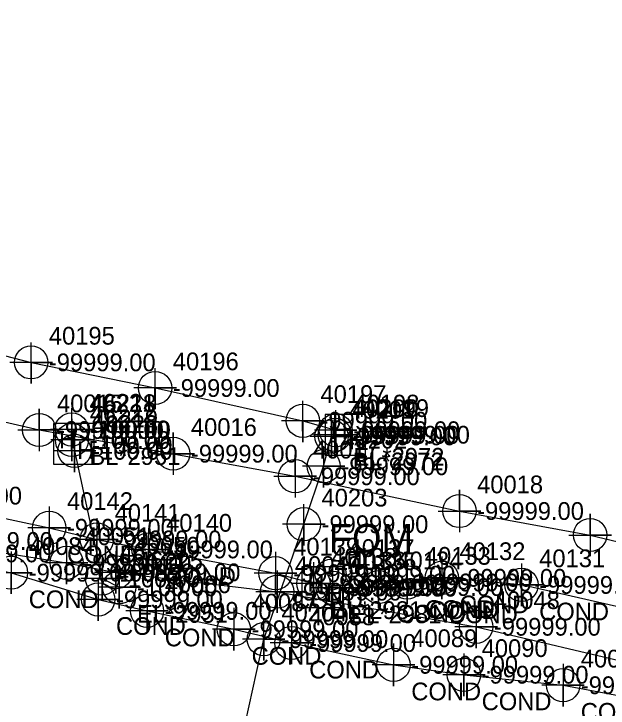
# Model space of a CAD drawing. Extents: x 2083698 to 2094313, y 743246 to 752873.
# Drawn here: x 2090821 to 2090904.8, y 744569.6 to 744667.4 of the extents above; entities that cross this region are included whole.
import ezdxf

# ---------------------------------------------------------------- set-up
doc = ezdxf.new("R2010")
doc.units = 0
for name, color, linetype in [('COGO Default Chain', 7, 'Continuous'), ('COGO Default Curve', 7, 'Continuous'), ('COGO Default Parcel', 7, 'Continuous'), ('COGO Default Point Number', 7, 'Continuous'), ('COGO Default Spiral', 7, 'Continuous'), ('Default Symbol CELL', 7, 'Continuous'), ('Default Symbol Cogo Number', 7, 'Continuous'), ('Exist Other Culture Fence Line', 7, 'Continuous'), ('Exist Property Corner CELL', 7, 'Continuous'), ('Exist Property Corner Cogo Comment', 7, 'Continuous'), ('Exist Property Deed Book Text', 7, 'Continuous'), ('Exist Property Iron Pin CELL', 7, 'Continuous'), ('Exist Property Iron Pin Cogo Elevation', 7, 'Continuous'), ('Exist Property Iron Pin Cogo Number', 7, 'Continuous'), ('Exist Property Iron Pin Leader', 7, 'Continuous'), ('Exist Property Iron Pin Text', 7, 'Continuous'), ('Exist Property Line', 7, 'Continuous'), ('Exist Property Line Leader', 7, 'Continuous'), ('Exist Property Monument Leader', 7, 'Continuous'), ('Exist Property Monument Text', 7, 'Continuous'), ('Exist Property Owner Text', 7, 'Continuous'), ('Exist Right of Way Line', 7, 'Continuous'), ('Exist Right of Way Line Leader', 7, 'Continuous'), ('Exist Right of Way Line Text', 7, 'Continuous'), ('Exist Utilities Gas UG Line SUE LOS B', 7, 'Continuous'), ('Exist Utilities Other Located Object CELL', 7, 'Continuous'), ('Exist Utilities Other Located Object Text', 7, 'Continuous'), ('Exist Utilities Power Joint Use Telephone Cogo Elevation', 7, 'Continuous'), ('Exist Utilities Power Joint Use Telephone Cogo Number', 7, 'Continuous'), ('Exist Utilities Power UG Cable SUE LOS B', 7, 'Continuous'), ('Exist Utilities Telephone UG Conduit SUE LOS B', 7, 'Continuous'), ('Exist Utilities TV UG Cable SUE LOS B', 7, 'Continuous'), ('Exist Utilities Water UG Line SUE LOS B', 7, 'Continuous'), ('Old_Level_20', 7, 'Continuous'), ('Scratch_Level_0', 7, 'Continuous'), ('Scratch_Level_2', 7, 'Continuous'), ('Scratch_Level_3', 7, 'Continuous'), ('Scratch_Level_5', 7, 'Continuous')]:
    doc.layers.add(name, color=color, linetype=linetype)

msp = doc.modelspace()

# ---------------------------------------------------------------- linework, layer by layer
at = {"layer": 'COGO Default Curve'}
for points in [[(2090821.585, 744608.753), (2090827.585, 744608.753), (2090824.585, 744608.753), (2090824.585, 744611.753), (2090824.585, 744605.753)], [(2090840.465, 744605.417), (2090846.465, 744605.417), (2090843.465, 744605.417), (2090843.465, 744608.417), (2090843.465, 744602.417)], [(2090857.667, 744602.233), (2090863.667, 744602.233), (2090860.667, 744602.233), (2090860.667, 744605.233), (2090860.667, 744599.233)], [(2090880.812, 744597.333), (2090886.812, 744597.333), (2090883.812, 744597.333), (2090883.812, 744600.333), (2090883.812, 744594.333)], [(2090899.238, 744593.955), (2090905.238, 744593.955), (2090902.238, 744593.955), (2090902.238, 744596.955), (2090902.238, 744590.955)]]:
    msp.add_lwpolyline(points, dxfattribs=at)
for centre in [(2090824.585, 744608.753), (2090843.465, 744605.417), (2090860.667, 744602.233), (2090883.812, 744597.333), (2090902.238, 744593.955)]:
    msp.add_circle(centre, 2.344, dxfattribs=at)
at = {"layer": 'COGO Default Point Number'}
for points in [[(2090828.444, 744593.031), (2090828.444, 744587.031), (2090828.444, 744590.031), (2090831.444, 744590.031), (2090825.444, 744590.031)], [(2090835.382, 744591.689), (2090835.382, 744585.689), (2090835.382, 744588.689), (2090838.382, 744588.689), (2090832.382, 744588.689)], [(2090858.125, 744588.967), (2090858.125, 744582.967), (2090858.125, 744585.967), (2090861.125, 744585.967), (2090855.125, 744585.967)], [(2090886.18, 744584.02), (2090886.18, 744578.02), (2090886.18, 744581.02), (2090889.18, 744581.02), (2090883.18, 744581.02)]]:
    msp.add_lwpolyline(points, dxfattribs=at)
for centre in [(2090828.444, 744590.031), (2090835.382, 744588.689), (2090858.125, 744585.967), (2090886.18, 744581.02)]:
    msp.add_circle(centre, 2.344, dxfattribs=at)
at = {"layer": 'COGO Default Spiral'}
msp.add_line((2090829.526, 744606.646), (2090829.526, 744606.646), dxfattribs=at)
msp.add_lwpolyline([(2090826.576, 744603.921), (2090832.326, 744603.921), (2090832.326, 744609.671), (2090826.576, 744609.671), (2090826.576, 744603.921)], dxfattribs=at)
at = {"layer": 'Exist Property Deed Book Text'}
msp.add_line((2090864.484, 744586.601), (2090864.484, 744586.601), dxfattribs=at)
msp.add_lwpolyline([(2090861.609, 744583.726), (2090867.359, 744583.726), (2090867.359, 744589.476), (2090861.609, 744589.476), (2090861.609, 744583.726)], dxfattribs=at)
at = {"layer": 'Exist Property Iron Pin CELL'}
for p, q in [((2090864.87, 744610.948), (2090864.87, 744605.223)), ((2090870.595, 744610.948), (2090864.87, 744610.948)), ((2090870.595, 744605.223), (2090870.595, 744610.948)), ((2090867.732, 744608.085), (2090867.732, 744608.085)), ((2090864.87, 744605.223), (2090870.595, 744605.223))]:
    msp.add_line(p, q, dxfattribs=at)
at = {"layer": 'Exist Property Iron Pin Text'}
for points in [[(2090829.15, 744611.832), (2090829.15, 744605.832), (2090829.15, 744608.832), (2090832.15, 744608.832), (2090826.15, 744608.832)], [(2090829.196, 744610.348), (2090829.196, 744604.348), (2090829.196, 744607.348), (2090832.196, 744607.348), (2090826.196, 744607.348)], [(2090829.547, 744608.818), (2090829.547, 744602.818), (2090829.547, 744605.818), (2090832.547, 744605.818), (2090826.547, 744605.818)], [(2090833.438, 744590.822), (2090833.438, 744584.822), (2090833.438, 744587.822), (2090836.438, 744587.822), (2090830.438, 744587.822)], [(2090835.861, 744589.588), (2090835.861, 744583.588), (2090835.861, 744586.588), (2090838.861, 744586.588), (2090832.861, 744586.588)]]:
    msp.add_lwpolyline(points, dxfattribs=at)
for centre in [(2090829.15, 744608.832), (2090829.196, 744607.348), (2090829.547, 744605.818), (2090833.438, 744587.822), (2090835.861, 744586.588)]:
    msp.add_circle(centre, 2.344, dxfattribs=at)
at = {"layer": 'Exist Property Line Leader'}
for points in [[(2090825.995, 744597.974), (2090825.995, 744591.974), (2090825.995, 744594.974), (2090828.995, 744594.974), (2090822.995, 744594.974)], [(2090832.713, 744596.332), (2090832.713, 744590.332), (2090832.713, 744593.332), (2090835.713, 744593.332), (2090829.713, 744593.332)], [(2090839.967, 744594.92), (2090839.967, 744588.92), (2090839.967, 744591.92), (2090842.967, 744591.92), (2090836.967, 744591.92)], [(2090820.602, 744591.645), (2090820.602, 744585.645), (2090820.602, 744588.645), (2090823.602, 744588.645), (2090817.602, 744588.645)], [(2090857.878, 744591.562), (2090857.878, 744585.562), (2090857.878, 744588.562), (2090860.878, 744588.562), (2090854.878, 744588.562)], [(2090881.325, 744590.918), (2090881.325, 744584.918), (2090881.325, 744587.918), (2090884.325, 744587.918), (2090878.325, 744587.918)], [(2090863.242, 744590.112), (2090863.242, 744584.112), (2090863.242, 744587.112), (2090866.242, 744587.112), (2090860.242, 744587.112)], [(2090876.446, 744590.265), (2090876.446, 744584.265), (2090876.446, 744587.265), (2090879.446, 744587.265), (2090873.446, 744587.265)], [(2090892.562, 744589.919), (2090892.562, 744583.919), (2090892.562, 744586.919), (2090895.562, 744586.919), (2090889.562, 744586.919)], [(2090865.945, 744589.525), (2090865.945, 744583.525), (2090865.945, 744586.525), (2090868.945, 744586.525), (2090862.945, 744586.525)], [(2090872.431, 744589.622), (2090872.431, 744583.622), (2090872.431, 744586.622), (2090875.431, 744586.622), (2090869.431, 744586.622)], [(2090832.902, 744587.88), (2090832.902, 744581.88), (2090832.902, 744584.88), (2090835.902, 744584.88), (2090829.902, 744584.88)], [(2090839.777, 744586.263), (2090839.777, 744580.263), (2090839.777, 744583.263), (2090842.777, 744583.263), (2090836.777, 744583.263)], [(2090852.021, 744583.672), (2090852.021, 744577.672), (2090852.021, 744580.672), (2090855.021, 744580.672), (2090849.021, 744580.672)], [(2090860.137, 744581.736), (2090860.137, 744575.736), (2090860.137, 744578.736), (2090863.137, 744578.736), (2090857.137, 744578.736)], [(2090874.53, 744578.658), (2090874.53, 744572.658), (2090874.53, 744575.658), (2090877.53, 744575.658), (2090871.53, 744575.658)], [(2090884.456, 744577.262), (2090884.456, 744571.262), (2090884.456, 744574.262), (2090887.456, 744574.262), (2090881.456, 744574.262)], [(2090898.426, 744575.782), (2090898.426, 744569.782), (2090898.426, 744572.782), (2090901.426, 744572.782), (2090895.426, 744572.782)]]:
    msp.add_lwpolyline(points, dxfattribs=at)
for centre in [(2090825.995, 744594.974), (2090832.713, 744593.332), (2090839.967, 744591.92), (2090820.602, 744588.645), (2090857.878, 744588.562), (2090881.325, 744587.918), (2090863.242, 744587.112), (2090872.431, 744586.622), (2090876.446, 744587.265), (2090892.562, 744586.919), (2090865.945, 744586.525), (2090832.902, 744584.88), (2090839.777, 744583.263), (2090852.021, 744580.672), (2090860.137, 744578.736), (2090874.53, 744575.658), (2090884.456, 744574.262), (2090898.426, 744572.782)]:
    msp.add_circle(centre, 2.344, dxfattribs=at)
at = {"layer": 'Exist Right of Way Line Text'}
for points in [[(2090823.405, 744621.1), (2090823.438, 744615.285), (2090823.421, 744618.285), (2090826.438, 744618.285), (2090820.438, 744618.285)], [(2090840.879, 744617.488), (2090840.912, 744611.673), (2090840.895, 744614.673), (2090843.912, 744614.673), (2090837.912, 744614.673)], [(2090861.694, 744612.876), (2090861.727, 744607.061), (2090861.71, 744610.061), (2090864.727, 744610.061), (2090858.727, 744610.061)], [(2090866.338, 744611.538), (2090866.371, 744605.723), (2090866.354, 744608.723), (2090869.371, 744608.723), (2090863.371, 744608.723)], [(2090865.753, 744610.666), (2090865.786, 744604.851), (2090865.769, 744607.851), (2090868.786, 744607.851), (2090862.786, 744607.851)], [(2090866.227, 744610.88), (2090866.26, 744605.065), (2090866.243, 744608.065), (2090869.26, 744608.065), (2090863.26, 744608.065)], [(2090864.645, 744606.456), (2090864.678, 744600.641), (2090864.661, 744603.641), (2090867.678, 744603.641), (2090861.678, 744603.641)], [(2090861.844, 744598.287), (2090861.877, 744592.472), (2090861.86, 744595.472), (2090864.877, 744595.472), (2090858.877, 744595.472)], [(2090856.192, 744582.089), (2090856.225, 744576.274), (2090856.208, 744579.274), (2090859.225, 744579.274), (2090853.225, 744579.274)]]:
    msp.add_lwpolyline(points, dxfattribs=at)
for centre in [(2090823.438, 744618.285), (2090840.912, 744614.673), (2090861.727, 744610.061), (2090866.371, 744608.723), (2090865.786, 744607.851), (2090866.26, 744608.065), (2090864.678, 744603.641), (2090861.877, 744595.472), (2090856.225, 744579.274)]:
    msp.add_circle(centre, 2.344, dxfattribs=at)
at = {"layer": 'Exist Utilities Gas UG Line SUE LOS B'}
msp.add_lwpolyline([(2090756.472, 744620.936), (2090779.93, 744617.286), (2090802.115, 744613.944), (2090824.585, 744608.753), (2090843.465, 744605.417), (2090860.667, 744602.233), (2090883.812, 744597.333), (2090902.238, 744593.955), (2090922.783, 744589.068), (2090941.584, 744583.971), (2090962.88, 744577.699), (2090982.419, 744572.409), (2091006.165, 744566.527), (2091026.733, 744561.149), (2091049.918, 744554.523), (2091063.295, 744550.877), (2091078.655, 744545.84), (2091093.018, 744541.678), (2091104.999, 744537.876), (2091116.633, 744533.938), (2091142.583, 744527.278)], dxfattribs=at)
at = {"layer": 'Exist Utilities Other Located Object CELL'}
for radius in [2.18, 0.24]:
    msp.add_circle((2090865.683, 744588.36), radius, dxfattribs=at)
at = {"layer": 'Exist Utilities Power UG Cable SUE LOS B'}
msp.add_lwpolyline([(2090829.15, 744608.832), (2090829.196, 744607.348), (2090829.547, 744605.818), (2090833.438, 744587.822), (2090835.861, 744586.588)], dxfattribs=at)
at = {"layer": 'Exist Utilities Telephone UG Conduit SUE LOS B'}
for points in [[(2090533.955, 744667.396), (2090555.365, 744662.881), (2090577, 744659.506), (2090598.411, 744655.977), (2090608.703, 744653.228), (2090623.205, 744652.004), (2090640.358, 744648.662), (2090647.763, 744648.151), (2090669.474, 744645.41), (2090691.771, 744642.142), (2090713.126, 744639.578), (2090737.955, 744638.372), (2090758.508, 744633.144), (2090776.704, 744628.866), (2090800.561, 744624.168), (2090823.438, 744618.285), (2090840.912, 744614.673), (2090861.727, 744610.061), (2090866.371, 744608.723)], [(2090826.992, 744485.617), (2090829.437, 744487.68), (2090831.334, 744489.708), (2090834.431, 744496.44), (2090839.279, 744513.707), (2090844.288, 744532.696), (2090847.289, 744545.815), (2090852.626, 744562.848), (2090856.225, 744579.274), (2090861.877, 744595.472), (2090864.678, 744603.641), (2090865.786, 744607.851), (2090866.26, 744608.065)]]:
    msp.add_lwpolyline(points, dxfattribs=at)
at = {"layer": 'Exist Utilities TV UG Cable SUE LOS B'}
for points in [[(2090533.056, 744663.356), (2090553.675, 744660.704), (2090577.287, 744654.547), (2090597.199, 744647.757), (2090613.836, 744642.498), (2090627.805, 744639.054), (2090650.47, 744634.21), (2090670.864, 744630.423), (2090699.957, 744623.254), (2090720.234, 744618.7), (2090739.648, 744615.865), (2090760.855, 744611.546), (2090782.339, 744605.996), (2090804.592, 744599.504), (2090825.995, 744594.974), (2090832.713, 744593.332), (2090839.967, 744591.92), (2090857.878, 744588.562), (2090863.242, 744587.112)], [(2090768.261, 744600.588), (2090780.32, 744597.904), (2090790.623, 744595.483), (2090808.734, 744591.357), (2090820.602, 744588.645), (2090832.902, 744584.88), (2090839.777, 744583.263), (2090852.021, 744580.672), (2090860.137, 744578.736), (2090874.53, 744575.658), (2090884.456, 744574.262), (2090898.426, 744572.782), (2090912.772, 744570.12)], [(2090968.736, 744567.161), (2090966.091, 744567.779), (2090959.757, 744569.665), (2090948.059, 744572.875), (2090932.676, 744576.714), (2090917.479, 744581.336), (2090908.66, 744583.248), (2090892.562, 744586.919), (2090881.325, 744587.918), (2090876.446, 744587.265), (2090872.431, 744586.622), (2090865.945, 744586.525)]]:
    msp.add_lwpolyline(points, dxfattribs=at)
at = {"layer": 'Exist Utilities Water UG Line SUE LOS B'}
msp.add_lwpolyline([(2090759.368, 744604.965), (2090792.334, 744596.691), (2090808.938, 744593.11), (2090828.444, 744590.031), (2090835.382, 744588.689), (2090858.125, 744585.967), (2090886.18, 744581.02), (2090909.716, 744575.465), (2090923.455, 744572.37), (2090937.458, 744568.468), (2090954.848, 744562.99), (2090972.991, 744556.852), (2090988.291, 744552.969), (2091007.283, 744548.202), (2091023.723, 744544.583), (2091042.729, 744540.431), (2091047.01, 744539.597)], dxfattribs=at)

# ---------------------------------------------------------------- texts
at = {"layer": 'COGO Default Chain'}
for p in [(2090827.085, 744607.503), (2090845.965, 744604.167), (2090863.167, 744600.983), (2090886.312, 744596.083)]:
    msp.add_text('-99999.00', height=2.5, dxfattribs=at).set_placement(p)
at = {"layer": 'COGO Default Parcel'}
msp.add_text('40137', height=2.5, dxfattribs=at).set_placement((2090868.183, 744590.86))
at = {"layer": 'COGO Default Spiral'}
for p in [(2090827.367, 744606.172), (2090829.931, 744604.652)]:
    msp.add_text('H', height=2.5, dxfattribs=at).set_placement(p)
at = {"layer": 'Default Symbol CELL'}
for s, p in [('40142', (2090828.495, 744597.474)), ('40141', (2090835.213, 744595.832)), ('40140', (2090842.467, 744594.42)), ('40084', (2090823.102, 744591.145)), ('40139', (2090860.378, 744591.062)), ('40132', (2090883.825, 744590.418)), ('40138', (2090865.742, 744589.612)), ('40133', (2090878.946, 744589.765)), ('40131', (2090895.062, 744589.419)), ('40135', (2090868.445, 744589.025)), ('40134', (2090874.931, 744589.122)), ('40085', (2090835.402, 744587.38)), ('40086', (2090842.277, 744585.763)), ('40087', (2090854.521, 744583.172)), ('40088', (2090862.637, 744581.236)), ('40089', (2090877.03, 744578.158)), ('40090', (2090886.956, 744576.762)), ('40091', (2090900.926, 744575.282))]:
    msp.add_text(s, height=2.5, dxfattribs=at).set_placement(p)
at = {"layer": 'Default Symbol Cogo Number'}
for p in [(2090807.092, 744598.254), (2090828.495, 744593.724), (2090835.213, 744592.082), (2090842.467, 744590.67), (2090811.234, 744590.107), (2090823.102, 744587.395), (2090860.378, 744587.312), (2090883.825, 744586.668), (2090865.742, 744585.862), (2090878.946, 744586.015), (2090895.062, 744585.669), (2090868.445, 744585.275), (2090874.931, 744585.372), (2090835.402, 744583.63), (2090842.277, 744582.013), (2090854.521, 744579.422), (2090862.637, 744577.486), (2090877.03, 744574.408), (2090886.956, 744573.012), (2090900.926, 744571.532)]:
    msp.add_text('-99999.00', height=2.5, dxfattribs=at).set_placement(p)
at = {"layer": 'Exist Other Culture Fence Line'}
msp.add_text('-100.00', height=2.5, dxfattribs=at).set_placement((2090832.026, 744605.396))
at = {"layer": 'Exist Property Corner CELL'}
for s, p in [('COND', (2090828.495, 744589.974)), ('COND', (2090835.213, 744588.332)), ('COND', (2090842.467, 744586.92)), ('COND', (2090823.102, 744583.645)), ('COND', (2090860.378, 744583.562)), ('COND', (2090883.825, 744582.918)), ('BL*2981 COND', (2090865.742, 744582.112)), ('EL*2981 COND', (2090868.445, 744581.525)), ('COND', (2090874.931, 744581.622)), ('COND', (2090878.946, 744582.265)), ('COND', (2090895.062, 744581.919)), ('COND', (2090835.402, 744579.88)), ('COND', (2090842.277, 744578.263)), ('COND', (2090854.521, 744575.672)), ('COND', (2090862.637, 744573.736)), ('COND', (2090877.03, 744570.658)), ('COND', (2090886.956, 744569.262)), ('COND', (2090900.926, 744567.782))]:
    msp.add_text(s, height=2.5, dxfattribs=at).set_placement(p)
at = {"layer": 'Exist Property Corner Cogo Comment'}
msp.add_text('-99999.00', height=2.5, dxfattribs=at).set_placement((2090866.984, 744585.351))
at = {"layer": 'Exist Property Deed Book Text'}
for p in [(2090862.395, 744585.953), (2090864.969, 744584.493)]:
    msp.add_text('H', height=2.5, dxfattribs=at).set_placement(p)
at = {"layer": 'Exist Property Iron Pin CELL'}
for p in [(2090865.648, 744607.493), (2090868.22, 744606.028)]:
    msp.add_text('H', height=2.5, dxfattribs=at).set_placement(p)
at = {"layer": 'Exist Property Iron Pin Cogo Elevation'}
msp.add_text('-99999.00', height=2.5, dxfattribs=at).set_placement((2090870.232, 744606.835))
at = {"layer": 'Exist Property Iron Pin Cogo Number'}
msp.add_text('40199', height=2.5, dxfattribs=at).set_placement((2090870.232, 744610.585))
at = {"layer": 'Exist Property Iron Pin Leader'}
for s, p in [('46221', (2090831.65, 744611.332)), ('46222', (2090831.696, 744609.848)), ('46223', (2090832.047, 744608.318)), ('46224', (2090835.938, 744590.322)), ('46225', (2090838.361, 744589.088))]:
    msp.add_text(s, height=2.5, dxfattribs=at).set_placement(p)
at = {"layer": 'Exist Property Line'}
for p in [(2090811.438, 744591.86), (2090830.944, 744588.781), (2090837.882, 744587.439), (2090860.625, 744584.717), (2090888.68, 744579.77)]:
    msp.add_text('-99999.00', height=2.5, dxfattribs=at).set_placement(p)
at = {"layer": 'Exist Property Monument Leader'}
for s, p in [('BL*2951', (2090831.65, 744603.832)), ('EL*2951', (2090838.361, 744581.588))]:
    msp.add_text(s, height=2.5, dxfattribs=at).set_placement(p)
at = {"layer": 'Exist Property Monument Text'}
for p in [(2090831.65, 744607.582), (2090831.696, 744606.098), (2090832.047, 744604.568), (2090835.938, 744586.572), (2090838.361, 744585.338)]:
    msp.add_text('-100.00', height=2.5, dxfattribs=at).set_placement(p)
at = {"layer": 'Exist Property Owner Text'}
msp.add_text('40136', height=2.5, dxfattribs=at).set_placement((2090866.984, 744589.101))
at = {"layer": 'Exist Right of Way Line'}
for s, p in [('40051', (2090830.944, 744592.531)), ('40050', (2090837.882, 744591.189)), ('40049', (2090860.625, 744588.467)), ('40048', (2090888.68, 744583.52))]:
    msp.add_text(s, height=2.5, dxfattribs=at).set_placement(p)
at = {"layer": 'Exist Right of Way Line Leader'}
for s, p in [('40195', (2090825.938, 744620.785)), ('40196', (2090843.412, 744617.173)), ('40197', (2090864.227, 744612.561)), ('40198', (2090868.871, 744611.223)), ('40201', (2090868.286, 744610.351)), ('40200', (2090868.76, 744610.565)), ('40202', (2090867.178, 744606.141)), ('40203', (2090864.377, 744597.972)), ('40204', (2090858.725, 744581.774))]:
    msp.add_text(s, height=2.5, dxfattribs=at).set_placement(p)
at = {"layer": 'Exist Utilities Other Located Object Text'}
msp.add_text('FOM', height=4, dxfattribs=at).set_placement((2090865.403, 744591.502))
at = {"layer": 'Exist Utilities Power Joint Use Telephone Cogo Elevation'}
msp.add_text('-100.00', height=2.5, dxfattribs=at).set_placement((2090831.79, 744607.524))
at = {"layer": 'Exist Utilities Power Joint Use Telephone Cogo Number'}
msp.add_text('46218', height=2.5, dxfattribs=at).set_placement((2090831.79, 744611.274))
at = {"layer": 'Old_Level_20'}
for s, p in [('40015', (2090827.085, 744611.253)), ('40016', (2090845.965, 744607.917)), ('40017', (2090863.167, 744604.733)), ('40018', (2090886.312, 744599.833))]:
    msp.add_text(s, height=2.5, dxfattribs=at).set_placement(p)
at = {"layer": 'Scratch_Level_0'}
msp.add_text('-99999.00', height=2.5, dxfattribs=at).set_placement((2090868.183, 744587.11))
at = {"layer": 'Scratch_Level_2'}
for p in [(2090825.938, 744617.035), (2090843.412, 744613.423), (2090864.227, 744608.811), (2090868.871, 744607.473), (2090868.286, 744606.601), (2090868.76, 744606.815), (2090867.178, 744602.391), (2090864.377, 744594.222), (2090858.725, 744578.024)]:
    msp.add_text('-99999.00', height=2.5, dxfattribs=at).set_placement(p)
at = {"layer": 'Scratch_Level_3'}
for s, p in [('BL*2972', (2090868.76, 744603.065)), ('EL*2972', (2090868.871, 744603.723))]:
    msp.add_text(s, height=2.5, dxfattribs=at).set_placement(p)
at = {"layer": 'Scratch_Level_5'}
msp.add_text('46219', height=2.5, dxfattribs=at).set_placement((2090832.026, 744609.146))

doc.saveas('drawing.dxf')
